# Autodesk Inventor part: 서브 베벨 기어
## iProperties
Created: 2012-07
Part Number: 서브 베벨 기어
Material: Steel, Mild
Document SubType Name: Modeling
Designer: SeoGD™ [www.esajin.kr]
Categories: <?xml version="1.0" encoding="UTF-16"?> <MemberInstance><Categories><FamilyTemplate><FamilyTemplateParameter ValueType="xs:double" Id="1" ObjectReferenceKey="da
Mass: 60.9118 g
Surface Area: 34.3074 cm^2
Volume: 7.7496 cm^3
Density: 7.86 g/cm^3
CustomPartVersion: 1
Author: SeoGD™ [www.esajin.kr]
